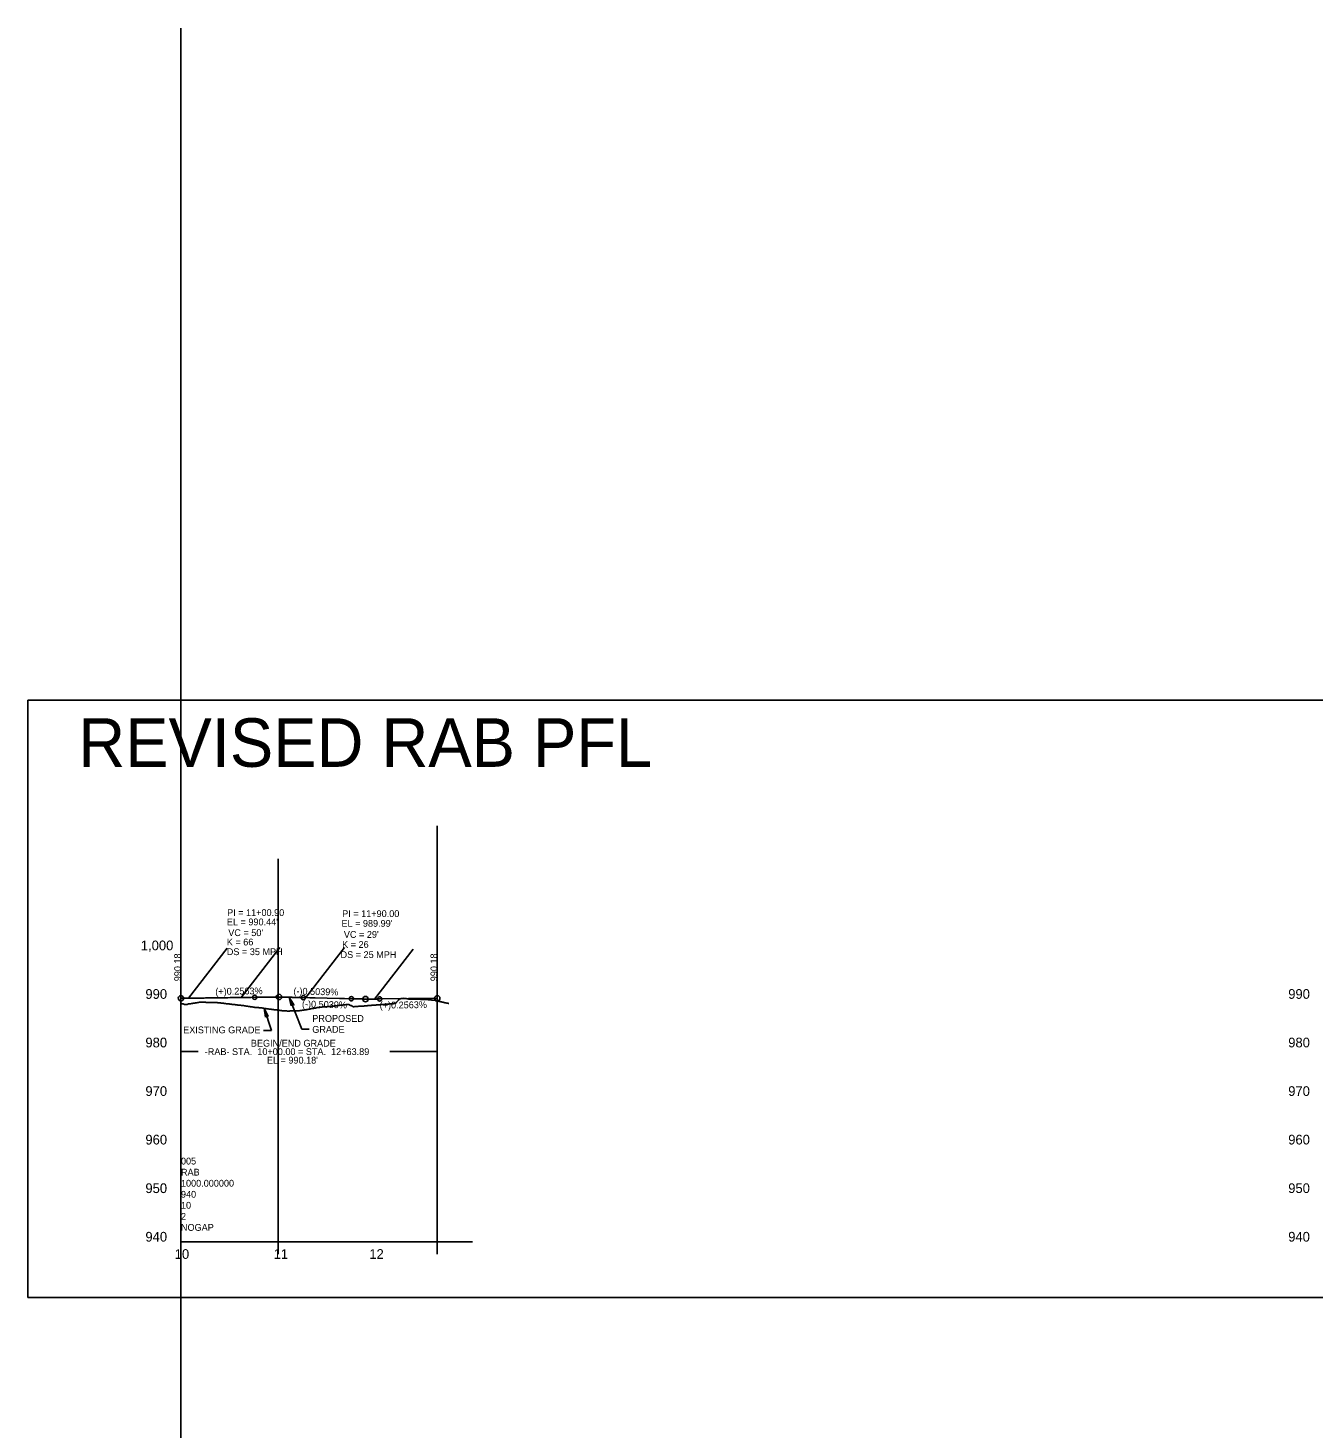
# Model space of a CAD drawing. Extents: x 1615624 to 1632571, y 894455 to 913418.
# Drawn here: x 1619961 to 1621285, y 901414 to 902856 of the extents above; entities that cross this region are included whole.
import ezdxf

# ---------------------------------------------------------------- set-up
doc = ezdxf.new("R2010")
doc.units = 0
for name, color, linetype in [('Exist Profile Cell', 7, 'Continuous'), ('Exist Vertical Profile Ground Line', 7, 'Continuous'), ('Exist Vertical Profile Horizontal Axis Label Major', 7, 'Continuous'), ('Exist Vertical Profile Vertical Axis Label', 7, 'Continuous'), ('Prop Terminator CELL', 7, 'Continuous'), ('Prop Vertical Profile Curve Label', 7, 'Continuous'), ('Prop Vertical Profile Grade', 7, 'Continuous'), ('Prop Vertical Profile Grade Label', 7, 'Continuous'), ('Prop VPI Label', 7, 'Continuous'), ('Scratch_Level_6', 7, 'Continuous')]:
    doc.layers.add(name, color=color, linetype=linetype)

msp = doc.modelspace()

# ---------------------------------------------------------------- linework, layer by layer
at = {"layer": 'Exist Profile Cell'}
for q in [(1620118.7, 902855.6), (1620418.7, 901605.6), (1620118.7, 900355.6)]:
    msp.add_line((1620118.7, 901605.6), q, dxfattribs=at)
at = {"layer": 'Exist Vertical Profile Ground Line'}
for points in [[(1620118.7, 901851.1), (1620119.3, 901851), (1620119.9, 901850.9), (1620120.5, 901850.8), (1620121, 901850.6), (1620121.6, 901850.4), (1620122.2, 901850.2), (1620122.8, 901850), (1620124, 901849.9), (1620124.7, 901850.1), (1620125.2, 901850.2), (1620125.8, 901850.4), (1620126.4, 901850.6), (1620127, 901850.7), (1620127.6, 901850.7), (1620128.1, 901850.8), (1620128.7, 901850.9), (1620129.3, 901851), (1620129.9, 901851.1), (1620130.5, 901851.2), (1620131.1, 901851.3), (1620131.7, 901851.4), (1620132.3, 901851.5), (1620132.9, 901851.6), (1620133.5, 901851.7), (1620134.1, 901851.8), (1620134.7, 901851.8), (1620135.3, 901851.9), (1620135.8, 901852), (1620136.4, 901852.1), (1620137, 901852.2), (1620137.6, 901852.3), (1620138.8, 901852.4), (1620139.4, 901852.4), (1620140, 901852.4), (1620140.6, 901852.4), (1620141.2, 901852.3), (1620141.8, 901852.3), (1620142.4, 901852.3), (1620142.9, 901852.3), (1620143.5, 901852.3), (1620144.1, 901852.3), (1620144.7, 901852.2), (1620145.3, 901852.2), (1620145.9, 901852.2), (1620146.5, 901852.2), (1620147.1, 901852.2), (1620147.7, 901852.2), (1620148.3, 901852.1), (1620148.9, 901852.1), (1620149.5, 901852.1), (1620150.1, 901852.1), (1620150.6, 901852.1), (1620151.2, 901852.1), (1620151.8, 901852.1), (1620152.4, 901852), (1620153, 901852), (1620153.6, 901852), (1620154.2, 901852), (1620154.8, 901852), (1620155.4, 901852), (1620156, 901852), (1620156.6, 901851.9), (1620157.3, 901851.9), (1620157.7, 901851.9), (1620158.3, 901851.8), (1620158.9, 901851.8), (1620159.5, 901851.7), (1620160.1, 901851.6), (1620160.7, 901851.5), (1620161.3, 901851.5), (1620161.9, 901851.4), (1620162.5, 901851.3), (1620163.1, 901851.2), (1620163.7, 901851.2), (1620164.3, 901851.1), (1620164.9, 901851), (1620165.4, 901850.9), (1620166, 901850.9), (1620166.6, 901850.8), (1620167.2, 901850.7), (1620167.8, 901850.6), (1620168.4, 901850.6), (1620169, 901850.5), (1620169.6, 901850.4), (1620170.2, 901850.4), (1620170.8, 901850.3), (1620171.4, 901850.2), (1620172, 901850.1), (1620172.6, 901850.1), (1620173.1, 901850), (1620173.7, 901849.9), (1620174.3, 901849.9), (1620174.9, 901849.8), (1620175.5, 901849.7), (1620176.1, 901849.6), (1620176.7, 901849.6), (1620177.3, 901849.5), (1620177.9, 901849.4), (1620178.5, 901849.4), (1620179.1, 901849.3)], [(1620298.1, 901847.9), (1620298.7, 901848), (1620299.2, 901848), (1620299.8, 901848), (1620300.4, 901848.1), (1620301, 901848.1), (1620301.6, 901848.2), (1620302.2, 901848.2), (1620302.8, 901848.2), (1620303.4, 901848.3), (1620304, 901848.3), (1620304.6, 901848.4), (1620305.2, 901848.4), (1620305.8, 901848.5), (1620306.4, 901848.5), (1620306.9, 901848.5), (1620307.5, 901848.6), (1620308.1, 901848.6), (1620308.7, 901848.7), (1620309.3, 901848.7), (1620309.9, 901848.8), (1620310.5, 901848.8), (1620311.1, 901848.9), (1620311.7, 901848.9), (1620312.3, 901848.9), (1620312.9, 901849), (1620313.5, 901849), (1620314, 901849.1), (1620314.6, 901849.1), (1620315.2, 901849.2), (1620315.8, 901849.2), (1620316.4, 901849.3), (1620317, 901849.3), (1620317.6, 901849.4), (1620318.2, 901849.4), (1620318.8, 901849.5), (1620319.4, 901849.5), (1620320, 901849.6), (1620320.6, 901849.6), (1620321.2, 901849.6), (1620321.7, 901849.7), (1620322.3, 901849.7), (1620322.9, 901849.8), (1620323.5, 901849.8), (1620324.1, 901849.9), (1620324.7, 901849.9), (1620325.3, 901850), (1620325.9, 901850), (1620326.5, 901850.1), (1620327.1, 901850.1), (1620327.7, 901850.2), (1620328.3, 901850.2), (1620328.8, 901850.3), (1620329.4, 901850.3), (1620330, 901850.4), (1620330.6, 901850.4), (1620331.2, 901850.5), (1620331.8, 901850.5), (1620332.4, 901850.5), (1620333, 901850.6), (1620333.6, 901850.6), (1620334.2, 901850.7), (1620334.8, 901850.7), (1620335.4, 901850.8), (1620336, 901850.8), (1620336.5, 901850.9), (1620337.1, 901850.9), (1620337.7, 901851), (1620338.6, 901851), (1620338.9, 901851), (1620339.6, 901851.4), (1620340.1, 901851.9), (1620340.7, 901852.6), (1620341.3, 901853.2), (1620341.9, 901853.9), (1620342.5, 901854.5), (1620343.1, 901855.2), (1620343.7, 901855.9), (1620344.2, 901855.9), (1620344.8, 901856), (1620345.4, 901856.1), (1620346, 901856.2), (1620346.6, 901856.3), (1620347.2, 901856.4), (1620348.1, 901856.5), (1620348.4, 901856.4), (1620349, 901856.3), (1620349.6, 901856.3), (1620350.2, 901856.2), (1620350.8, 901856.1), (1620351.3, 901856), (1620351.9, 901855.9), (1620352.5, 901855.8), (1620353.2, 901855.7), (1620353.7, 901855.7), (1620354.3, 901855.7), (1620354.9, 901855.6), (1620355.5, 901855.6), (1620356.1, 901855.5), (1620356.7, 901855.5), (1620357.5, 901855.4)], [(1620357.5, 901855.4), (1620357.9, 901855.4), (1620358.5, 901855.4), (1620359, 901855.4), (1620359.6, 901855.4), (1620360.2, 901855.4), (1620360.8, 901855.4), (1620361.4, 901855.4), (1620362, 901855.4), (1620362.6, 901855.4), (1620363.2, 901855.4), (1620363.8, 901855.4), (1620364.4, 901855.4), (1620365, 901855.4), (1620365.6, 901855.3), (1620366.1, 901855.3), (1620366.7, 901855.3), (1620367.3, 901855.3), (1620367.9, 901855.3), (1620368.6, 901855.3), (1620369.1, 901855.3), (1620369.7, 901855.3), (1620370.3, 901855.2), (1620370.9, 901855.2), (1620371.5, 901855.2), (1620372.1, 901855.1), (1620372.7, 901855.1), (1620373.3, 901855), (1620373.8, 901854.9), (1620374.4, 901854.9), (1620375, 901854.8), (1620375.6, 901854.7), (1620376.2, 901854.7), (1620376.8, 901854.6), (1620377.4, 901854.5), (1620378, 901854.5), (1620378.6, 901854.4), (1620380.4, 901854.2), (1620380.9, 901854), (1620381.5, 901853.9), (1620382.1, 901853.8), (1620382.7, 901853.7), (1620383.3, 901853.5), (1620383.9, 901853.4), (1620384.5, 901853.3), (1620385.1, 901853.1), (1620385.7, 901853), (1620386.3, 901852.9), (1620386.9, 901852.7), (1620387.5, 901852.6), (1620388.1, 901852.5), (1620388.6, 901852.3), (1620389.2, 901852.2), (1620389.8, 901852.1), (1620390.4, 901851.9), (1620391, 901851.8), (1620391.6, 901851.7), (1620392.2, 901851.6), (1620392.8, 901851.4), (1620393.4, 901851.3), (1620394, 901851.2), (1620394.6, 901851.1)], [(1620179.1, 901849.3), (1620179.7, 901849.2), (1620180.2, 901849.2), (1620180.8, 901849.1), (1620181.4, 901849.1), (1620182, 901849), (1620182.6, 901848.9), (1620183.3, 901848.9), (1620183.8, 901848.8), (1620184.4, 901848.7), (1620185, 901848.6), (1620185.6, 901848.5), (1620186.2, 901848.4), (1620186.8, 901848.3), (1620187.4, 901848.2), (1620187.9, 901848.1), (1620188.5, 901848.1), (1620189.1, 901848), (1620189.7, 901847.9), (1620190.3, 901847.8), (1620190.9, 901847.7), (1620191.5, 901847.6), (1620192.2, 901847.5), (1620192.7, 901847.4), (1620193.3, 901847.3), (1620193.9, 901847.3), (1620194.7, 901847.1), (1620195, 901847.1), (1620195.6, 901847), (1620196.2, 901847), (1620196.8, 901846.9), (1620197.4, 901846.9), (1620198, 901846.8), (1620198.6, 901846.8), (1620199.2, 901846.7), (1620199.8, 901846.7), (1620200.4, 901846.6), (1620201, 901846.6), (1620201.6, 901846.5), (1620202.2, 901846.5), (1620202.7, 901846.4), (1620203.3, 901846.3), (1620203.9, 901846.2), (1620204.5, 901846.1), (1620205.1, 901846), (1620205.7, 901845.9), (1620206.3, 901845.9), (1620206.9, 901845.7), (1620207.5, 901845.7), (1620208.1, 901845.6), (1620208.7, 901845.5), (1620209.3, 901845.4), (1620209.8, 901845.3), (1620210.4, 901845.3), (1620211, 901845.2), (1620211.6, 901845.1), (1620212.2, 901845), (1620212.8, 901844.9), (1620213.4, 901844.8), (1620214, 901844.8), (1620214.6, 901844.7), (1620215.2, 901844.6), (1620215.8, 901844.6), (1620216.4, 901844.5), (1620217, 901844.4), (1620217.5, 901844.4), (1620218.1, 901844.3), (1620218.7, 901844.2), (1620219.3, 901844.1), (1620219.9, 901844.1), (1620220.5, 901844), (1620221.3, 901843.9), (1620221.7, 901843.9), (1620222.3, 901843.8), (1620222.9, 901843.7), (1620223.5, 901843.7), (1620224.1, 901843.6), (1620224.8, 901843.5), (1620225.2, 901843.5), (1620225.8, 901843.5), (1620226.4, 901843.5), (1620227.1, 901843.4), (1620227.6, 901843.4), (1620228.2, 901843.3), (1620228.8, 901843.3), (1620229.4, 901843.3), (1620230, 901843.3), (1620230.6, 901843.3), (1620231.2, 901843.4), (1620231.8, 901843.4), (1620232.3, 901843.4), (1620232.9, 901843.4), (1620233.5, 901843.4), (1620234.1, 901843.5), (1620234.7, 901843.5), (1620235.3, 901843.5), (1620235.9, 901843.5), (1620236.5, 901843.6), (1620237.1, 901843.5), (1620237.7, 901843.5), (1620238.3, 901843.4)], [(1620238.3, 901843.4), (1620238.9, 901843.5), (1620239.5, 901843.6), (1620240, 901843.6), (1620240.6, 901843.7), (1620241.2, 901843.8), (1620241.8, 901843.8), (1620242.4, 901843.9), (1620243, 901844), (1620243.6, 901844.1), (1620244.2, 901844.2), (1620244.8, 901844.3), (1620245.4, 901844.3), (1620246, 901844.4), (1620246.6, 901844.5), (1620247.1, 901844.6), (1620247.7, 901844.7), (1620248.3, 901844.8), (1620248.9, 901844.9), (1620249.5, 901845), (1620250.1, 901845.2), (1620250.7, 901845.3), (1620251.3, 901845.4), (1620251.9, 901845.5), (1620252.5, 901845.6), (1620253.3, 901845.8), (1620253.7, 901845.8), (1620254.3, 901845.9), (1620255, 901846), (1620255.4, 901846.1), (1620256, 901846.2), (1620256.6, 901846.3), (1620257.2, 901846.4), (1620257.8, 901846.6), (1620258.4, 901846.7), (1620259, 901846.8), (1620259.6, 901846.9), (1620260.2, 901847), (1620260.8, 901847.1), (1620261.4, 901847.1), (1620261.9, 901847.2), (1620262.5, 901847.3), (1620263.1, 901847.3), (1620263.7, 901847.4), (1620264.3, 901847.5), (1620264.9, 901847.5), (1620265.5, 901847.6), (1620266.1, 901847.6), (1620266.7, 901847.7), (1620267.3, 901847.7), (1620267.9, 901847.8), (1620268.5, 901847.8), (1620269.1, 901847.8), (1620269.6, 901847.9), (1620270.2, 901847.9), (1620270.8, 901848), (1620271.4, 901848), (1620272, 901848.1), (1620272.6, 901848.2), (1620273.8, 901848.3), (1620274.4, 901848.4), (1620275, 901848.4), (1620275.6, 901848.5), (1620276.2, 901848.5), (1620276.7, 901848.6), (1620277.6, 901848.7), (1620277.9, 901848.7), (1620278.5, 901848.8), (1620279.1, 901848.8), (1620279.7, 901848.9), (1620280.3, 901849), (1620280.9, 901849), (1620281.5, 901849.1), (1620282.1, 901849.2), (1620282.7, 901849.2), (1620283.3, 901849.3), (1620283.9, 901849.4), (1620284.4, 901849.4), (1620285, 901849.5), (1620285.6, 901849.6), (1620286.2, 901849.6), (1620286.8, 901849.7), (1620287.4, 901849.7), (1620288, 901849.8), (1620288.6, 901849.9), (1620289.2, 901849.9), (1620289.8, 901850), (1620290.4, 901850), (1620291, 901850), (1620291.6, 901850), (1620292.1, 901849.7), (1620292.7, 901849.4), (1620293.3, 901849.1), (1620293.9, 901848.9), (1620294.5, 901848.6), (1620295.1, 901848.3), (1620295.7, 901848), (1620296.3, 901847.8), (1620296.9, 901847.8), (1620297.5, 901847.9), (1620298.1, 901847.9)]]:
    msp.add_lwpolyline(points, dxfattribs=at)
at = {"layer": 'Prop Terminator CELL'}
for points in [[(1620232, 901848.6), (1620230.1, 901857.5), (1620235, 901849.7), (1620233.1, 901850.2)], [(1620205.6, 901837.1), (1620204.2, 901846.2), (1620208.6, 901838.1), (1620206.7, 901838.7)]]:
    msp.add_lwpolyline(points, close=True, dxfattribs=at)
at = {"layer": 'Prop Vertical Profile Curve Label'}
for centre in [(1620194.6, 901857.5), (1620244.6, 901857.2), (1620294.2, 901856), (1620323.2, 901855.8)]:
    msp.add_circle(centre, 2.25, dxfattribs=at)
at = {"layer": 'Prop Vertical Profile Grade'}
for p, q in [((1620118.7, 901856.5), (1620194.6, 901857.5)), ((1620244.6, 901857.2), (1620294.2, 901856)), ((1620323.2, 901855.8), (1620382.6, 901856.5))]:
    msp.add_line(p, q, dxfattribs=at)
for points in [[(1620194.6, 901857.5), (1620195.6, 901857.5), (1620196.6, 901857.5), (1620197.6, 901857.6), (1620198.6, 901857.6), (1620199.6, 901857.6), (1620200.6, 901857.6), (1620201.6, 901857.6), (1620202.6, 901857.6), (1620203.6, 901857.6), (1620204.6, 901857.6), (1620205.6, 901857.6), (1620206.6, 901857.6), (1620207.6, 901857.6), (1620208.6, 901857.6), (1620209.6, 901857.6), (1620210.6, 901857.6), (1620211.6, 901857.6), (1620212.6, 901857.6), (1620213.6, 901857.6), (1620214.6, 901857.6), (1620215.6, 901857.6), (1620216.6, 901857.6), (1620217.6, 901857.6), (1620218.6, 901857.6), (1620219.6, 901857.6), (1620220.6, 901857.6), (1620221.6, 901857.6), (1620222.6, 901857.6), (1620223.6, 901857.6), (1620224.6, 901857.6), (1620225.6, 901857.5), (1620226.6, 901857.5), (1620227.6, 901857.5), (1620228.6, 901857.5), (1620229.6, 901857.5), (1620230.6, 901857.5), (1620231.6, 901857.5), (1620232.6, 901857.5), (1620233.6, 901857.4), (1620234.6, 901857.4), (1620235.6, 901857.4), (1620236.6, 901857.4), (1620237.6, 901857.4), (1620238.6, 901857.3), (1620239.6, 901857.3), (1620240.6, 901857.3), (1620241.6, 901857.3), (1620242.6, 901857.3), (1620243.6, 901857.2), (1620244.6, 901857.2)], [(1620294.2, 901856), (1620294.8, 901855.9), (1620295.3, 901855.9), (1620295.9, 901855.9), (1620296.5, 901855.9), (1620297.1, 901855.9), (1620297.7, 901855.9), (1620298.2, 901855.9), (1620298.8, 901855.9), (1620299.4, 901855.8), (1620300, 901855.8), (1620300.6, 901855.8), (1620301.1, 901855.8), (1620301.7, 901855.8), (1620302.3, 901855.8), (1620302.9, 901855.8), (1620303.5, 901855.8), (1620304, 901855.8), (1620304.6, 901855.8), (1620305.2, 901855.8), (1620305.8, 901855.8), (1620306.4, 901855.7), (1620306.9, 901855.7), (1620307.5, 901855.7), (1620308.1, 901855.7), (1620308.7, 901855.7), (1620309.3, 901855.7), (1620309.8, 901855.7), (1620310.4, 901855.7), (1620311, 901855.7), (1620311.6, 901855.7), (1620312.2, 901855.7), (1620312.7, 901855.7), (1620313.3, 901855.7), (1620313.9, 901855.7), (1620314.5, 901855.7), (1620315.1, 901855.7), (1620315.6, 901855.7), (1620316.2, 901855.7), (1620316.8, 901855.7), (1620317.4, 901855.7), (1620318, 901855.7), (1620318.5, 901855.7), (1620319.1, 901855.7), (1620319.7, 901855.7), (1620320.3, 901855.7), (1620320.9, 901855.8), (1620321.4, 901855.8), (1620322, 901855.8), (1620322.6, 901855.8), (1620323.2, 901855.8)]]:
    msp.add_spline(points, degree=3, dxfattribs=at)
at = {"layer": 'Prop VPI Label'}
for p, q in [((1620118.7, 901856.5), (1620118.7, 901801.5)), ((1620194.6, 901857.5), (1620216.8, 901857.8)), ((1620244.6, 901857.2), (1620222.3, 901857.8)), ((1620230.1, 901857.5), (1620243.2, 901824.8)), ((1620294.2, 901856), (1620305.9, 901855.7)), ((1620323.2, 901855.8), (1620311.4, 901855.6)), ((1620382.6, 901856.5), (1620382.6, 901801.5)), ((1620204.2, 901846.2), (1620211.9, 901823.4)), ((1620211.9, 901823.4), (1620203.7, 901823.4)), ((1620243.2, 901824.8), (1620250.6, 901824.8)), ((1620118.7, 901801.5), (1620136.5, 901801.5)), ((1620333.6, 901801.5), (1620382.6, 901801.5))]:
    msp.add_line(p, q, dxfattribs=at)
msp.add_lwpolyline([(1619961.2, 902163.6), (1622670.1, 902163.6), (1622670.1, 901548.5), (1619961.2, 901548.5)], close=True, dxfattribs=at)
for centre in [(1620118.7, 901856.5), (1620219.6, 901857.8), (1620308.7, 901855.6), (1620382.6, 901856.5)]:
    msp.add_circle(centre, 2.75, dxfattribs=at)
at = {"layer": 'Scratch_Level_6'}
for p, q in [((1620382.6, 901593.1), (1620382.6, 902033.9)), ((1620218.7, 901593.1), (1620218.7, 902000)), ((1620126.5, 901856.6), (1620166.2, 901908.1)), ((1620180.7, 901857.3), (1620220.4, 901908.8)), ((1620247.3, 901857.1), (1620287, 901908.6)), ((1620317.9, 901855.7), (1620357.6, 901907.2)), ((1620118.7, 901856.3), (1620215.2, 901857.6)), ((1620126.5, 901856.6), (1620126.5, 901856.6)), ((1620126.5, 901856.4), (1620126.5, 901856.4)), ((1620323, 901855.4), (1620215.2, 901857.6)), ((1620247.3, 901856.9), (1620247.3, 901856.9))]:
    msp.add_line(p, q, dxfattribs=at)

# ---------------------------------------------------------------- texts
at = {"layer": 'Exist Profile Cell'}
for s, p in [('005', (1620118.7, 901685.3)), ('RAB', (1620118.7, 901673.9)), ('1000.000000', (1620118.7, 901662.5)), ('940', (1620118.7, 901651.1)), ('10', (1620118.7, 901639.8)), ('2', (1620118.7, 901628.4)), ('NOGAP', (1620118.7, 901617))]:
    msp.add_text(s, height=7, dxfattribs=at).set_placement(p)
at = {"layer": 'Exist Vertical Profile Horizontal Axis Label Major'}
for s, p in [('10', (1620112.3, 901588.1)), ('11', (1620214.1, 901588.1)), ('12', (1620312.6, 901588.1))]:
    msp.add_text(s, height=10, dxfattribs=at).set_placement(p)
at = {"layer": 'Exist Vertical Profile Vertical Axis Label'}
for s, p in [('1,000', (1620077.4, 901905.9)), ('990', (1620082.1, 901855.9)), ('990', (1621258.6, 901855.9)), ('980', (1620082.1, 901805.9)), ('980', (1621258.6, 901805.9)), ('970', (1620082.1, 901755.9)), ('970', (1621258.6, 901755.9)), ('960', (1620082.1, 901705.9)), ('960', (1621258.6, 901705.9)), ('950', (1620082.1, 901655.9)), ('950', (1621258.6, 901655.9)), ('940', (1620082.1, 901605.9)), ('940', (1621258.6, 901605.9))]:
    msp.add_text(s, height=10, dxfattribs=at).set_placement(p)
at = {"layer": 'Prop Vertical Profile Curve Label'}
for s, p in [("VC = 50'", (1620167.4, 901920.5)), ("VC = 29'", (1620286.4, 901918.7))]:
    msp.add_text(s, height=7, dxfattribs=at).set_placement(p)
at = {"layer": 'Prop Vertical Profile Grade Label'}
for s, rotation, p in [('(+)0.2563%', 0.7343, (1620154.1, 901860)), ('(-)0.5039%', 358.5568, (1620234.4, 901860.5)), ('(-)0.5039%', 358.5568, (1620243.2, 901847.2)), ('(+)0.2563%', 0.7342, (1620323.3, 901845.8))]:
    msp.add_text(s, height=7, rotation=rotation, dxfattribs=at).set_placement(p)
at = {"layer": 'Prop VPI Label'}
for s, height, p in [('REVISED RAB PFL', 50, (1620013, 902094.8)), ("EL = 990.44'", 7, (1620166, 901931.6)), ('PI = 11+00.90', 7, (1620166.2, 901941.2)), ('PI = 11+90.00', 7, (1620284.7, 901940.1)), ("EL = 989.99'", 7, (1620283.9, 901930.1)), ('K = 66', 7, (1620165.9, 901910.9)), ('K = 26', 7, (1620284.6, 901908.4)), ('DS = 35 MPH', 7, (1620165.9, 901900.9)), ('DS = 25 MPH', 7, (1620283, 901897.9)), ('PROPOSED ', 7, (1620253.9, 901832.2)), ('EXISTING GRADE', 7, (1620121, 901820.4)), ('GRADE', 7, (1620253.9, 901820.9)), ('BEGIN/END GRADE', 7, (1620190.7, 901806.7)), ('-RAB- STA.  10+00.00 = STA.  12+63.89', 7, (1620143.2, 901798)), ("EL = 990.18'", 7, (1620207.2, 901789.2))]:
    msp.add_text(s, height=height, dxfattribs=at).set_placement(p)
for p in [(1620118.7, 901874), (1620382.6, 901874)]:
    msp.add_text('990.18', height=7, rotation=90, dxfattribs=at).set_placement(p)

doc.saveas('drawing.dxf')
